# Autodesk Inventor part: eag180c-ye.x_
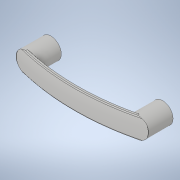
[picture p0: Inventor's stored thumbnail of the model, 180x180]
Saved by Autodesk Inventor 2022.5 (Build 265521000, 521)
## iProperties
Created: 2021-07
Part Number: eag180c-ye.x_
Material: 一般
Document SubType Name: Modeling
Designer: ImaoCorp
Density: 1 g/cm^3
Appearance: 既定
Sending System: SOLIDWORKS 2019-2019304
MC: AMD64
MC_MODEL: Intel64 Family 6 Model 60 Stepping 3, GenuineIntel
OS: Windows_NT
FRU: Parasolid Version 31.0, build 290,  9- 1-2019
FORMAT: text
GUISE: transmit
KEY: eag180c-ye
FILE: eag180c-ye.x_t
DATE: Thu Jul 29 14:22:05 2021
Author: ImaoCorp
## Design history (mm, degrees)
feature "Base1"
node "ソリッド1"
